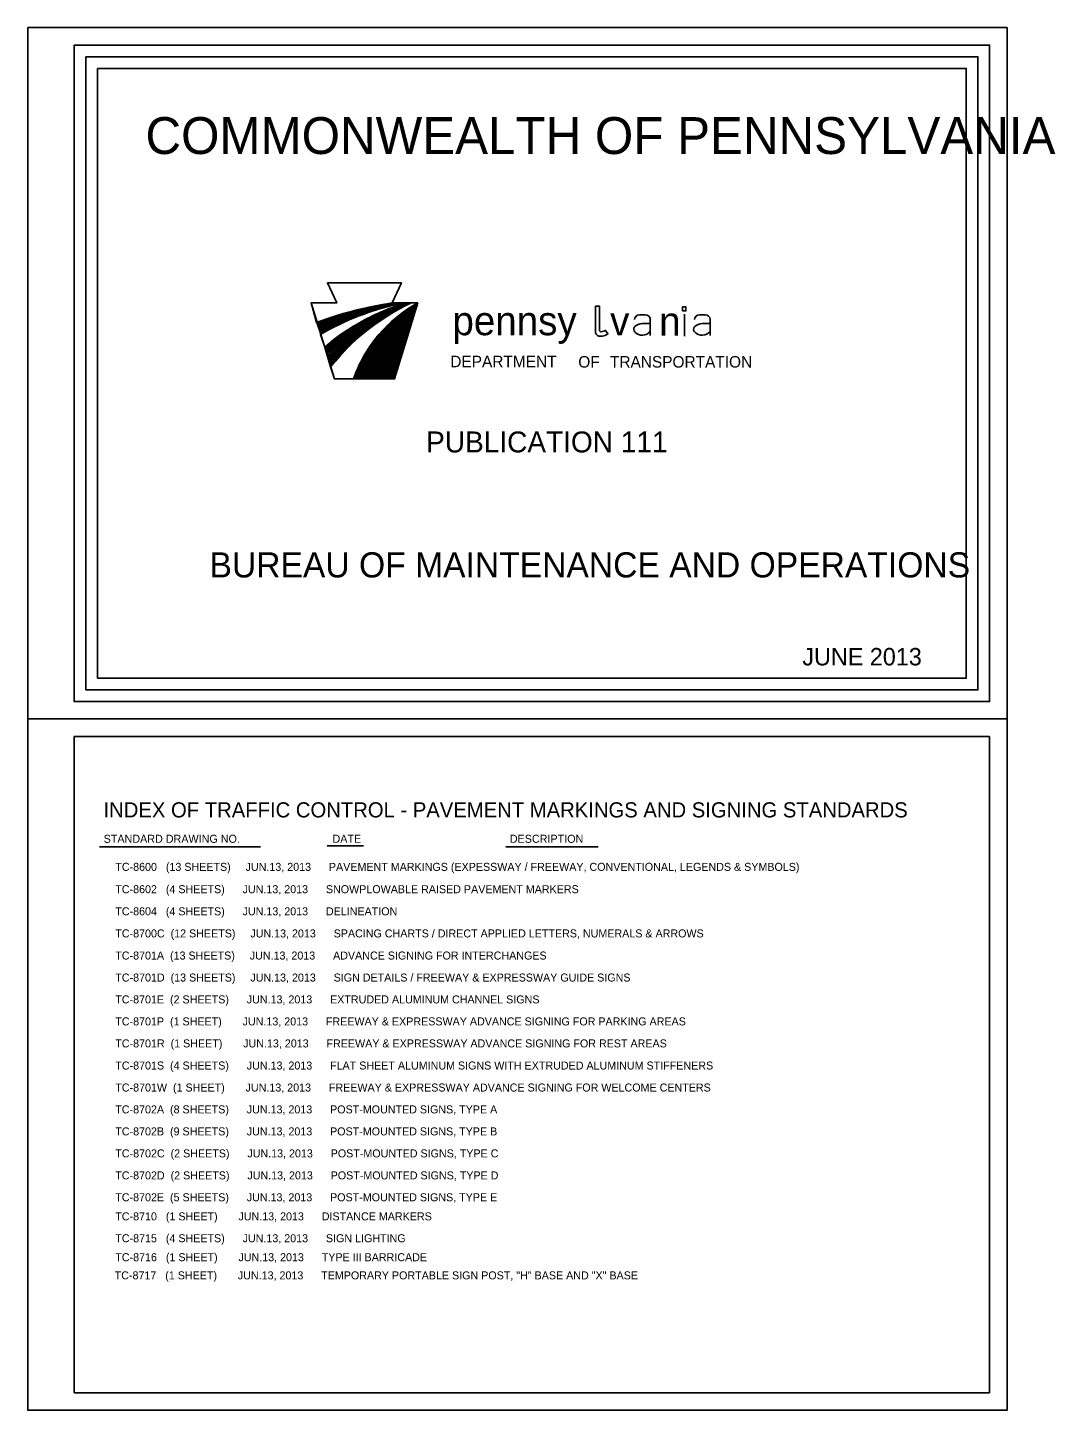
# Model space of a CAD drawing. Extents: x -2276 to -864, y 22 to 1210.
# Drawn here: x -1746 to -864, y 22 to 1210 of the extents above; entities that cross this region are included whole.
import ezdxf

# ---------------------------------------------------------------- set-up
doc = ezdxf.new("R2010")
doc.units = 0
for name, color, linetype in [('1', 7, 'Continuous'), ('2', 7, 'Continuous'), ('Level 1', 7, 'Continuous'), ('Level 2', 7, 'Continuous'), ('PLT-BNDY', 7, 'Continuous')]:
    doc.layers.add(name, color=color, linetype=linetype)

msp = doc.modelspace()

# ---------------------------------------------------------------- linework, layer by layer
at = {"layer": '1'}
for p, q in [((-1480.7, 973.7), (-1488.7, 990.9)), ((-1488.7, 990.9), (-1425.2, 990.9)), ((-1425.2, 990.9), (-1433.2, 973.7)), ((-1482.8, 908.4), (-1502.8, 973.7)), ((-1502.8, 973.7), (-1480.7, 973.7)), ((-1433.2, 973.7), (-1411.1, 973.7)), ((-1411.1, 973.7), (-1431.1, 908.4)), ((-1220.7, 963.5), (-1215.8, 963.5)), ((-1182.2, 964.1), (-1182.2, 945.2)), ((-1169.2, 963.5), (-1164.4, 963.5)), ((-1211.5, 956.1), (-1218.3, 956.1)), ((-1211.5, 959.3), (-1211.5, 945.7)), ((-1160, 956.1), (-1166.8, 956.1)), ((-1160, 959.3), (-1160, 945.7)), ((-1431.1, 908.4), (-1482.8, 908.4))]:
    msp.add_line(p, q, dxfattribs=at)
for points in [[(-1433.2, 973.7), (-1425.2, 990.9), (-1488.7, 990.9), (-1480.7, 973.7), (-1502.8, 973.7), (-1498.1, 956.7), (-1489.2, 960.1), (-1481.5, 962.6), (-1475.1, 964.5), (-1468.3, 966.4), (-1463.3, 967.7), (-1452.9, 970.1), (-1442.7, 972.1), (-1436.4, 973.1)], [(-1433.2, 973.7), (-1437.6, 973), (-1442.8, 972), (-1448.9, 970.8), (-1454.1, 969.7), (-1460.1, 968.4), (-1468, 966.4), (-1475.9, 964.2), (-1482.8, 962), (-1489.9, 959.7), (-1495.6, 957.6), (-1497.8, 956.8), (-1494.5, 946.7), (-1489.3, 949.8), (-1483.7, 952.7), (-1479.1, 955), (-1473.8, 957.6), (-1468.4, 959.9), (-1462.5, 962.3), (-1457.8, 964.1), (-1452.1, 966.1), (-1446.6, 967.8), (-1440.3, 969.7), (-1435.1, 971.2), (-1429.4, 972.5), (-1425.4, 973.7)], [(-1425.4, 973.7), (-1435.8, 971), (-1449.7, 966.9), (-1461.3, 962.8), (-1471.7, 958.5), (-1483.1, 953.1), (-1492.1, 948.2), (-1494.7, 946.6), (-1491.1, 935.6), (-1485.9, 940.1), (-1482.1, 943), (-1477.4, 946.4), (-1473.4, 949.1), (-1468.8, 952.1), (-1463.2, 955.4), (-1456.4, 959.3), (-1450.2, 962.4), (-1443.1, 965.7), (-1439.3, 967.2), (-1433.7, 969.5), (-1426.8, 971.8), (-1421.1, 973.7)], [(-1421.1, 973.7), (-1427.2, 971.6), (-1432.4, 969.9), (-1438.4, 967.5), (-1444.6, 965), (-1450.9, 962.1), (-1457.9, 958.4), (-1465, 954.4), (-1471.2, 950.5), (-1476.9, 946.8), (-1483, 942.2), (-1487.3, 938.8), (-1491.1, 935.6), (-1486.1, 918.8), (-1480, 926), (-1474.5, 932), (-1469.5, 937), (-1463.6, 942.7), (-1458.6, 947), (-1452.9, 951.6), (-1447.3, 956), (-1442.2, 959.3), (-1436.6, 962.9), (-1431, 966.2), (-1426.9, 968.6), (-1422, 971.3), (-1416.7, 973.7)], [(-1416.7, 973.7), (-1421.5, 971.7), (-1428.5, 967.9), (-1437, 962.6), (-1446.8, 956.1), (-1455, 949.9), (-1459.6, 946.3), (-1467.1, 939.4), (-1471.8, 934.7), (-1477.9, 928.3), (-1481.8, 923.7), (-1486.1, 918.8), (-1482.8, 908.4), (-1466.2, 908.4), (-1465.1, 911.3), (-1461.9, 919.2), (-1459.9, 923.2), (-1456.3, 929.7), (-1453.2, 934.9), (-1448.9, 941), (-1444.5, 946.4), (-1438.9, 952.5), (-1433.3, 958.1), (-1428.3, 962), (-1423.8, 965.7), (-1419.3, 968.7), (-1414.3, 971.8), (-1411.1, 973.7)], [(-1411.1, 973.7), (-1414.8, 971.4), (-1419, 968.8), (-1423.6, 965.6), (-1429.1, 961.5), (-1433.4, 957.9), (-1436.8, 954.5), (-1441, 950.1), (-1445.7, 944.8), (-1449.7, 939.9), (-1453.2, 934.9), (-1456.2, 930), (-1458.4, 926.1), (-1461.4, 920.4), (-1464.5, 912.7), (-1466.2, 908.4), (-1431.1, 908.4)], [(-1258.4, 971), (-1258.4, 948), (-1257.9, 946.7), (-1256.9, 945.7), (-1255.6, 945), (-1254.1, 945), (-1252.5, 945.1), (-1250.3, 945.7), (-1248.8, 946.5), (-1247.9, 947), (-1249.9, 950.1), (-1251.3, 949.5), (-1252.9, 949), (-1254.3, 948.8), (-1255.1, 949.8), (-1255.1, 971)], [(-1183.8, 966.8), (-1180.9, 966.8), (-1180.9, 970.2), (-1183.8, 970.2)]]:
    msp.add_lwpolyline(points, close=True, dxfattribs=at)
msp.add_circle((-1442.9, 923.8), 8.21, dxfattribs=at)
for centre, radius, start, end in [((-1381.6, 643.4), 334.3, 98.8803, 110.3962), ((-1377.1, 744.8), 233.5, 102.171, 120.2393), ((-1366.8, 790.7), 190.9, 106.6298, 130.6117), ((-1336, 800.8), 190.8, 115.3724, 141.7165), ((-1353.7, 869.2), 119.2, 118.798, 160.3663)]:
    msp.add_arc(centre, radius, start, end, dxfattribs=at)
for centre, major_axis, start_param, end_param in [((-1220.7, 959), (0, -4.57), 3.141593, 4.64997), ((-1215.8, 959), (0, 4.57), 4.789654, 6.283185), ((-1169.2, 959), (0, -4.57), 3.141593, 4.64997), ((-1164.4, 959), (0, 4.57), 4.789654, 6.283185), ((-1222.6, 951), (0, -3.23), 4.014, 5.498069), ((-1217.9, 945.7), (0, 10.4), 0.041523, 0.789828), ((-1171.2, 951), (0, -3.23), 4.014, 5.498069), ((-1166.4, 945.7), (0, 10.4), 0.041523, 0.789828), ((-1218.4, 954.9), (0, 9.09), 2.325877, 4.056693), ((-1167, 954.9), (0, 9.09), 2.325877, 4.056693)]:
    msp.add_ellipse(centre, major_axis=major_axis, ratio=0.96098, start_param=start_param, end_param=end_param, dxfattribs=at)
at = {"layer": '2'}
for p, q in [((-1496.7, 953.4), (-1480.6, 962.7)), ((-1496.2, 952.3), (-1475.5, 964.3)), ((-1495.9, 951.1), (-1470.9, 965.6)), ((-1495.5, 949.9), (-1466.4, 966.8)), ((-1495.1, 948.8), (-1462, 967.9)), ((-1494.8, 947.6), (-1457.9, 968.9)), ((-1490.8, 934.5), (-1425.5, 972.2)), ((-1490.6, 936), (-1431.3, 970.3)), ((-1490.4, 933.3), (-1420.5, 973.7)), ((-1490.1, 932.1), (-1428.8, 967.5)), ((-1485.1, 940.6), (-1438.6, 967.4)), ((-1482.3, 953.4), (-1454.2, 969.7)), ((-1477.2, 946.5), (-1447.7, 963.6)), ((-1469.4, 959.5), (-1450.3, 970.5)), ((-1461.3, 962.8), (-1446.6, 971.3)), ((-1454.7, 965.2), (-1443, 972)), ((-1449, 967.1), (-1439.4, 972.6)), ((-1445.7, 944.8), (-1414.4, 962.9)), ((-1444, 968.6), (-1436, 973.2)), ((-1443.1, 947.8), (-1413.9, 964.6)), ((-1440.4, 950.7), (-1413.4, 966.3)), ((-1439.1, 970), (-1432.8, 973.7)), ((-1437.6, 953.7), (-1412.8, 968)), ((-1434.4, 971.4), (-1430.4, 973.7)), ((-1434.4, 956.9), (-1412.3, 969.6)), ((-1430.5, 972.2), (-1427.9, 973.7)), ((-1429.5, 961.1), (-1411.8, 971.3)), ((-1425.8, 969.3), (-1418.1, 973.7)), ((-1425.6, 973.7), (-1425.5, 973.7)), ((-1421.4, 967.2), (-1411.3, 973)), ((-1497.3, 955.8), (-1491.9, 958.9)), ((-1497.1, 954.6), (-1486, 961)), ((-1489.7, 931), (-1449.6, 954.1)), ((-1456.9, 928.7), (-1418, 951.1)), ((-1455.7, 930.7), (-1417.5, 952.8)), ((-1454.4, 932.9), (-1417, 954.5)), ((-1453, 935.1), (-1416.5, 956.2)), ((-1451.4, 937.4), (-1415.9, 957.9)), ((-1449.8, 939.7), (-1415.4, 959.5)), ((-1447.8, 942.3), (-1414.9, 961.2)), ((-1489.4, 929.8), (-1456, 949)), ((-1489, 928.6), (-1461.5, 944.5)), ((-1488.7, 927.4), (-1465.7, 940.7)), ((-1463.5, 915.2), (-1421.6, 939.4)), ((-1462.7, 917), (-1421.1, 941)), ((-1462, 918.8), (-1420.6, 942.7)), ((-1461.2, 920.6), (-1420.1, 944.4)), ((-1460.2, 922.6), (-1419.5, 946.1)), ((-1459.1, 924.6), (-1419, 947.8)), ((-1458.1, 926.6), (-1418.5, 949.4)), ((-1488.3, 926.2), (-1469.3, 937.2)), ((-1488, 925), (-1472.6, 933.9)), ((-1487.6, 923.9), (-1475.6, 930.8)), ((-1487.3, 922.7), (-1478.2, 927.9)), ((-1465.6, 909.8), (-1423.1, 934.3)), ((-1465.6, 908.4), (-1423.7, 932.6)), ((-1464.9, 911.6), (-1422.6, 936)), ((-1464.2, 913.4), (-1422.1, 937.7)), ((-1463.2, 908.4), (-1424.2, 930.9)), ((-1460.8, 908.4), (-1424.7, 929.3)), ((-1458.4, 908.4), (-1425.2, 927.6)), ((-1486.9, 921.5), (-1480.8, 925)), ((-1486.6, 920.3), (-1483.1, 922.3)), ((-1486.2, 919.1), (-1485.4, 919.6)), ((-1456, 908.4), (-1425.7, 925.9)), ((-1453.6, 908.4), (-1426.2, 924.2)), ((-1451.2, 908.4), (-1426.8, 922.5)), ((-1448.8, 908.4), (-1427.3, 920.8)), ((-1446.4, 908.4), (-1427.8, 919.2)), ((-1444, 908.4), (-1428.3, 917.5)), ((-1441.6, 908.4), (-1428.8, 915.8)), ((-1439.2, 908.4), (-1429.3, 914.1)), ((-1436.8, 908.4), (-1429.8, 912.4)), ((-1434.3, 908.4), (-1430.4, 910.7)), ((-1431.9, 908.4), (-1430.9, 909.1))]:
    msp.add_line(p, q, dxfattribs=at)
at = {"layer": 'Level 1'}
for p, q in [((-1706.1, 601.2), (-920.1, 601.2)), ((-1706.1, 37.2), (-1706.1, 601.2)), ((-920.1, 601.2), (-920.1, 37.2)), ((-920.1, 37.2), (-1706.1, 37.2))]:
    msp.add_line(p, q, dxfattribs=at)
for points in [[(-1706.1, 1195.2), (-920.1, 1195.2), (-920.1, 631.2), (-1706.1, 631.2)], [(-1696.1, 1185.2), (-930.1, 1185.2), (-930.1, 641.2), (-1696.1, 641.2)], [(-1686.1, 1175.2), (-940.1, 1175.2), (-940.1, 651.2), (-1686.1, 651.2)]]:
    msp.add_lwpolyline(points, close=True, dxfattribs=at)
at = {"layer": 'Level 2'}
for p, q in [((-1684.4, 506.3), (-1546.3, 506.3)), ((-1488.9, 507.3), (-1457.8, 507.3)), ((-1335.5, 506.3), (-1256.1, 506.3)), ((-1670.9, 492.5), (-1670.9, 492.5)), ((-1670.9, 454.4), (-1670.9, 454.4)), ((-1670.9, 173.5), (-1670.9, 173.5))]:
    msp.add_line(p, q, dxfattribs=at)
at = {"layer": 'PLT-BNDY'}
for points in [[(-1746.1, 1210.2), (-905.1, 1210.2), (-905.1, 616.2), (-1746.1, 616.2)], [(-1746.1, 616.2), (-905.1, 616.2), (-905.1, 22.2), (-1746.1, 22.2)]]:
    msp.add_lwpolyline(points, close=True, dxfattribs=at)

# ---------------------------------------------------------------- texts
at = {"layer": '1'}
for s, p in [('v', (-1246, 945.7)), ('n', (-1203.9, 945.4))]:
    msp.add_text(s, height=24.8, dxfattribs=at).set_placement(p)
at = {"layer": '2'}
for s, height, p in [('pennsy ', 24.75, (-1381.4, 945.9)), ('DEPARTMENT', 9.9, (-1383.2, 918.4))]:
    msp.add_text(s, height=height, dxfattribs=at).set_placement(p)
for s, p in [('OF', (-1273.3, 918.1)), ('TRANSPORTATION', (-1246.1, 918.1))]:
    msp.add_text(s, height=9.9, rotation=360, dxfattribs=at).set_placement(p)
at = {"layer": 'Level 2'}
for s, height, p in [('COMMONWEALTH OF PENNSYLVANIA', 31.68, (-1645, 1101.6)), ('PUBLICATION 111', 18, (-1404, 845.2)), ('BUREAU OF MAINTENANCE AND OPERATIONS', 21.6, (-1590, 737.8)), ('JUNE 2013', 15, (-1080.9, 662.2)), ('INDEX OF TRAFFIC CONTROL - PAVEMENT MARKINGS AND SIGNING STANDARDS', 13, (-1681, 531.6)), ('STANDARD DRAWING NO.', 6.907, (-1680.9, 509.8)), ('DATE', 6.91, (-1484.4, 509.8)), ('DESCRIPTION', 6.907, (-1332.1, 509.8)), ('TC-8600   (13 SHEETS)     JUN.13, 2013      PAVEMENT MARKINGS (EXPESSWAY / FREEWAY, CONVENTIONAL, LEGENDS & SYMBOLS)', 6.8753, (-1670.9, 485.7)), ('TC-8602   (4 SHEETS)      JUN.13, 2013      SNOWPLOWABLE RAISED PAVEMENT MARKERS', 6.875, (-1670.9, 466.5)), ('TC-8604   (4 SHEETS)      JUN.13, 2013      DELINEATION', 6.875, (-1670.9, 447.5)), ('TC-8700C  (12 SHEETS)     JUN.13, 2013      SPACING CHARTS / DIRECT APPLIED LETTERS, NUMERALS & ARROWS', 6.8753, (-1670.9, 428.5)), ('TC-8701A  (13 SHEETS)     JUN.13, 2013      ADVANCE SIGNING FOR INTERCHANGES', 6.875, (-1670.9, 409.5)), ('TC-8701D  (13 SHEETS)     JUN.13, 2013      SIGN DETAILS / FREEWAY & EXPRESSWAY GUIDE SIGNS', 6.875, (-1670.9, 390.6)), ('TC-8701E  (2 SHEETS)      JUN.13, 2013      EXTRUDED ALUMINUM CHANNEL SIGNS', 6.875, (-1670.9, 371.8)), ('TC-8701P  (1 SHEET)       JUN.13, 2013      FREEWAY & EXPRESSWAY ADVANCE SIGNING FOR PARKING AREAS', 6.875, (-1670.9, 352.9)), ('TC-8701R  (1 SHEET)       JUN.13, 2013      FREEWAY & EXPRESSWAY ADVANCE SIGNING FOR REST AREAS', 6.875, (-1670.9, 334)), ('TC-8701S  (4 SHEETS)      JUN.13, 2013      FLAT SHEET ALUMINUM SIGNS WITH EXTRUDED ALUMINUM STIFFENERS', 6.8753, (-1670.9, 315)), ('TC-8701W  (1 SHEET)       JUN.13, 2013      FREEWAY & EXPRESSWAY ADVANCE SIGNING FOR WELCOME CENTERS', 6.875, (-1670.9, 296.1)), ('TC-8702A  (8 SHEETS)      JUN.13, 2013      POST-MOUNTED SIGNS, TYPE A', 6.875, (-1670.9, 277.3)), ('TC-8702B  (9 SHEETS)      JUN.13, 2013      POST-MOUNTED SIGNS, TYPE B', 6.875, (-1670.9, 258.4)), ('TC-8702C  (2 SHEETS)      JUN.13, 2013      POST-MOUNTED SIGNS, TYPE C', 6.875, (-1670.9, 239.5)), ('TC-8702D  (2 SHEETS)      JUN.13, 2013      POST-MOUNTED SIGNS, TYPE D', 6.875, (-1670.9, 220.6)), ('TC-8702E  (5 SHEETS)      JUN.13, 2013      POST-MOUNTED SIGNS, TYPE E', 6.875, (-1670.9, 201.8)), ('TC-8710   (1 SHEET)       JUN.13, 2013      DISTANCE MARKERS', 6.875, (-1670.9, 185.4)), ('TC-8715   (4 SHEETS)      JUN.13, 2013      SIGN LIGHTING', 6.875, (-1670.9, 166.6)), ('TC-8716   (1 SHEET)       JUN.13, 2013      TYPE III BARRICADE', 6.875, (-1670.9, 150.3)), ('TC-8717   (1 SHEET)       JUN.13, 2013      TEMPORARY PORTABLE SIGN POST, "H" BASE AND "X" BASE', 6.875, (-1671.4, 134.7))]:
    msp.add_text(s, height=height, dxfattribs=at).set_placement(p)

doc.saveas('drawing.dxf')
